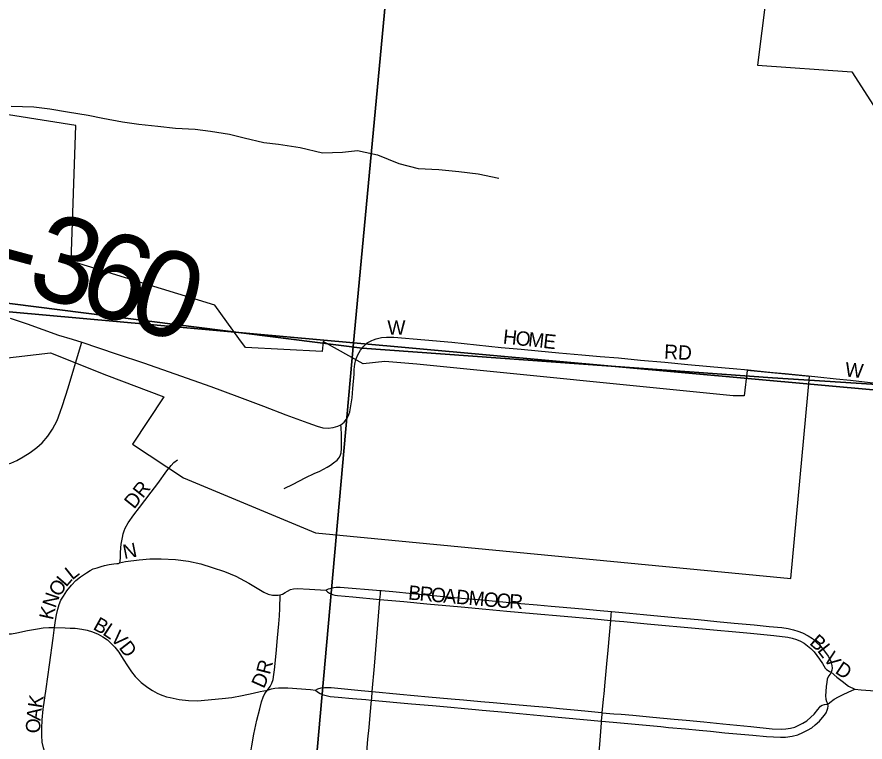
# Model space of a CAD drawing. Extents: x 1410790 to 1770854, y 566777 to 831614.
# Drawn here: x 1598681 to 1601638, y 712950 to 715480 of the extents above; entities that cross this region are included whole.
import ezdxf

# ---------------------------------------------------------------- set-up
doc = ezdxf.new("R2010")
doc.units = 0
for name, color, linetype in [('GM_X_City_Street', 7, 'Continuous'), ('GM_X_City_Street_Text', 7, 'Continuous'), ('GM_X_Corporation', 7, 'Continuous'), ('GM_X_County_Road', 7, 'Continuous'), ('GM_X_County_Road_Text', 7, 'Continuous'), ('GM_X_Minor_River', 7, 'Continuous'), ('GM_X_Section', 7, 'Continuous'), ('GM_X_Township', 7, 'Continuous'), ('GM_X_Township_Subdivision', 7, 'Continuous')]:
    doc.layers.add(name, color=color, linetype=linetype)

msp = doc.modelspace()

# ---------------------------------------------------------------- linework, layer by layer
at = {"layer": 'GM_X_City_Street'}
for points in [[(1598831.1, 714100.5), (1598839.6, 714124.1), (1598858.8, 714185.4), (1598902.2, 714329.5), (1598906.7, 714344.6)], [(1599863.4, 714286.9), (1599868.8, 714301), (1599878.2, 714317.7), (1599883.9, 714324.7), (1599889.6, 714331.7), (1599902.1, 714342.7), (1599917.8, 714351.5), (1599923.9, 714353.8), (1599933.4, 714357.2), (1599951.7, 714361.4), (1599968.8, 714363), (1599994.9, 714363), (1600102.7, 714353.6), (1600197, 714344.7), (1600368.8, 714327), (1600439.2, 714320.8), (1600498, 714314.5), (1600569.9, 714308.3), (1600650.1, 714301.5), (1600713.6, 714295.3), (1600777.7, 714290), (1600854.8, 714282.8), (1600939.2, 714274.9), (1601019.9, 714267.7), (1601150.1, 714255.7), (1601177.9, 714253.1)], [(1601441.1, 714227.7), (1601473.5, 714224.4), (1601536.5, 714217.1), (1601586.5, 714212.4), (1601636, 714207.2), (1601666.2, 714203.6), (1601704.8, 714199.9), (1601789.2, 714190.6), (1601837.1, 714185.3), (1601914.3, 714177.2)], [(1598359.7, 713924.1), (1598490.8, 713914.6), (1598538.5, 713911.1), (1598575, 713910.3), (1598606.2, 713912), (1598631.4, 713916.3), (1598658.7, 713923.5), (1598680, 713932.8), (1598702.6, 713945), (1598726.9, 713959.7), (1598750.1, 713977.6), (1598769, 713993.8), (1598787.7, 714017.3), (1598804.7, 714041.4), (1598820.6, 714071.7), (1598831.1, 714100.5)], [(1599038.1, 713575.7), (1599039.9, 713579.6), (1599040.8, 713583.9), (1599041.6, 713590.8), (1599041.9, 713600.9), (1599041.9, 713610.6), (1599042.8, 713627.9), (1599043.9, 713640), (1599045.9, 713651.9), (1599048, 713663.1), (1599051.4, 713676.3), (1599054.9, 713686.4), (1599058.3, 713695.6), (1599068.1, 713714.4), (1599087.8, 713742.5), (1599107.8, 713768.7), (1599126.4, 713792.6), (1599148.1, 713821.2)], [(1598811, 713349.6), (1598814.8, 713374.2), (1598818.3, 713394.1), (1598822.6, 713413.2), (1598827.8, 713429.7), (1598833.9, 713444.5), (1598842.6, 713459.2), (1598854.7, 713477.4), (1598870.4, 713497.4), (1598886, 713513), (1598901.6, 713526.1), (1598923.3, 713540.8), (1598935.4, 713548.1), (1598946.7, 713553.9), (1598959.8, 713558.2), (1598973.9, 713562.5), (1598985.9, 713565.6), (1599002.2, 713569), (1599018.7, 713571.3), (1599028.5, 713572.3), (1599034.8, 713573.4), (1599036.6, 713574.4), (1599038.1, 713575.7)], [(1599038.1, 713575.7), (1599058.5, 713579.3), (1599106.2, 713586.1), (1599143.3, 713588.7), (1599182.9, 713588.6), (1599233.2, 713586.8), (1599279.2, 713580.8), (1599321.7, 713572.1), (1599361.7, 713559), (1599404.2, 713545.2), (1599443.3, 713528.7), (1599489.3, 713504.4), (1599541.8, 713472.3), (1599556.3, 713466), (1599571.1, 713462.3), (1599582.8, 713462), (1599591.3, 713462.2), (1599598.7, 713463.6)], [(1599598.7, 713463.6), (1599606.5, 713466.4), (1599615.7, 713471.3), (1599623.6, 713476.6), (1599634.5, 713482.1), (1599645, 713484.3), (1599658.1, 713485.1), (1599700.2, 713483.3), (1599757.7, 713479.4)], [(1599757.7, 713479.4), (1599767, 713484.1), (1599776.2, 713487.1), (1599785.4, 713489), (1599793.1, 713490.1), (1599808, 713490), (1599948.7, 713478.8)], [(1599554.5, 713131.3), (1599563.6, 713143.9), (1599569.5, 713155), (1599574.1, 713168.6), (1599576.6, 713185.1), (1599578.1, 713201.4), (1599584.2, 713258.7), (1599589.4, 713313.4), (1599593.7, 713362), (1599596.5, 713390), (1599596.8, 713415.5), (1599598.7, 713463.6)], [(1599757.7, 713479.4), (1599763.6, 713473.7), (1599770.7, 713468.8), (1599780.9, 713464.3), (1599789.2, 713461.9), (1599798, 713460.7), (1599852.2, 713456), (1599946.1, 713447.4)], [(1599946.1, 713447.4), (1599947.6, 713466.1), (1599948.7, 713478.8)], [(1599948.7, 713478.8), (1599951.5, 713478.6), (1599991.2, 713474.7), (1600059.6, 713468.1), (1600180.1, 713456.5), (1600242.9, 713450.8), (1600301, 713445.6), (1600385.9, 713437.9), (1600437.4, 713433.3), (1600493.9, 713428.2), (1600543.3, 713423.7), (1600570.7, 713421.3), (1600652.6, 713414.5), (1600713.6, 713408.8), (1600753.7, 713405.1)], [(1599919.5, 713125.8), (1599926.9, 713214.6), (1599946.1, 713447.4)], [(1599946.1, 713447.4), (1600029.2, 713439.8), (1600109.3, 713432.5), (1600229.9, 713421.5), (1600315.9, 713413.6), (1600388.8, 713407), (1600480.9, 713398.6), (1600588.2, 713388.8), (1600694.3, 713379.2), (1600750.9, 713374)], [(1600750.9, 713374), (1600752.6, 713393.2), (1600753.7, 713405.1)], [(1600753.7, 713405.1), (1600778.7, 713402.8), (1600815.9, 713399.4), (1600865.3, 713394.8), (1600974.6, 713384.5), (1601055.3, 713376.9), (1601120.4, 713370.7), (1601181.1, 713365), (1601250.9, 713358.4), (1601303.7, 713353.4), (1601347.9, 713349.2), (1601369.5, 713345.5), (1601388.1, 713341.4), (1601403.2, 713336.4), (1601419.3, 713330.4), (1601439.9, 713320.8), (1601454.5, 713310.7), (1601466.6, 713299.7), (1601482.2, 713284.6), (1601496.3, 713267), (1601508.9, 713249.9), (1601517.4, 713234.3), (1601520, 713226.7), (1601522.2, 713217), (1601523.1, 713207.3), (1601522.5, 713200.9), (1601519.7, 713193.1)], [(1600721.5, 713052.3), (1600725.9, 713100), (1600727.5, 713118), (1600731.2, 713158.3), (1600737.1, 713222.2), (1600741.5, 713270.8), (1600746.2, 713322.9), (1600750.9, 713374)], [(1600750.9, 713374), (1600796.9, 713370.2), (1600878.5, 713362.5), (1601238.3, 713330.1), (1601319.8, 713321.6), (1601368.3, 713315.7), (1601383.8, 713312.6), (1601398.7, 713307.9), (1601412.8, 713301.7), (1601424.9, 713294.5), (1601436.9, 713285.9), (1601449.1, 713275.9), (1601460.1, 713264.5), (1601470.2, 713252), (1601479.5, 713239), (1601489.3, 713223.7), (1601498.8, 713208.1), (1601503.8, 713203), (1601508.9, 713199.1), (1601513.7, 713195.8), (1601519.7, 713193.1)], [(1598486.9, 713312.1), (1598543.6, 713326.3), (1598562, 713329.4), (1598581.7, 713330.9), (1598606.9, 713330.4), (1598628.8, 713328.4), (1598644.5, 713327.4), (1598661.2, 713327.9), (1598680.4, 713330.9), (1598717.8, 713338.8), (1598752, 713344.6), (1598772.2, 713347.9), (1598791.4, 713349.6), (1598811, 713349.6)], [(1598865.3, 712811.4), (1598854.5, 712818.6), (1598844.1, 712826), (1598832.2, 712836.3), (1598820.1, 712846.7), (1598809.7, 712858.9), (1598800.1, 712871.5), (1598790.9, 712887.2), (1598782.9, 712901.4), (1598776.4, 712917.5), (1598772.8, 712930.1), (1598768.8, 712949.7), (1598767, 712972.3), (1598767, 712997.4), (1598768.8, 713027.8), (1598772.3, 713065.1), (1598781.8, 713135.5), (1598793.9, 713218.8), (1598806.2, 713312.7), (1598811, 713349.6)], [(1598811, 713349.6), (1598848.1, 713348.6), (1598866.5, 713347.6), (1598883.6, 713346.6), (1598907, 713343.8), (1598925.1, 713340.4), (1598944, 713334), (1598963.6, 713325.7), (1598979.9, 713316.6), (1598996.1, 713306.1), (1599009.6, 713293.8), (1599021.8, 713280.4), (1599035.7, 713263), (1599051.2, 713238.5), (1599065.5, 713215.5), (1599080.3, 713194.7), (1599093.1, 713178.9), (1599102.9, 713167.9), (1599113.5, 713157.3), (1599136.5, 713139.6), (1599153.1, 713129.1), (1599169.3, 713120), (1599179.5, 713115.5), (1599188.6, 713112.4), (1599202.5, 713107.9), (1599214.9, 713104.9), (1599246.2, 713098.4), (1599278.3, 713095), (1599310.6, 713094), (1599396.6, 713101.4), (1599429.6, 713105.8), (1599466, 713111.8), (1599504.2, 713120.5), (1599528.5, 713126.6), (1599554.5, 713131.3)], [(1601519.7, 713193.1), (1601515.8, 713187.1), (1601510.4, 713179.2), (1601506.2, 713169.5), (1601504, 713159.2), (1601502.4, 713144.2), (1601500.8, 713126.1), (1601500.2, 713110.5), (1601501.2, 713099.7), (1601503.3, 713091.4), (1601508.3, 713081.9)], [(1601519.7, 713193.1), (1601539.9, 713176.5), (1601557.4, 713161.7), (1601580.4, 713145.2), (1601601.9, 713133.9)], [(1599506.7, 712736.3), (1599502, 712745.5), (1599494.2, 712764.6), (1599487.7, 712793.3), (1599486.3, 712832.4), (1599489.6, 712873), (1599494.7, 712908.9), (1599499.2, 712936.5), (1599506.5, 712977.6), (1599517.3, 713026.1), (1599526.9, 713066), (1599533.4, 713090.3), (1599539.1, 713106), (1599545.4, 713118.8), (1599554.5, 713131.3)], [(1599554.5, 713131.3), (1599568.4, 713135.6), (1599579.6, 713137.9), (1599592.7, 713138.9), (1599624.9, 713138.9), (1599703.9, 713132.6), (1599721.4, 713131.3)], [(1599721.4, 713131.3), (1599729.5, 713135.5), (1599741.5, 713139.2), (1599752.5, 713140.5), (1599761.9, 713140.5), (1599776, 713139.8), (1599799.8, 713137.5), (1599881.2, 713129.5), (1599919.5, 713125.8)], [(1599721.4, 713131.3), (1599728.7, 713124.8), (1599738.1, 713119.6), (1599745, 713116.1), (1599753.5, 713113), (1599772.4, 713109.3), (1599800.7, 713106.7), (1599850.8, 713102.2), (1599897.1, 713098.1), (1599916.9, 713096.3)], [(1601508.3, 713081.9), (1601514.9, 713087.9), (1601530.5, 713099), (1601545.2, 713107.7), (1601560.9, 713115.9), (1601578.7, 713124), (1601601.9, 713133.9)], [(1601601.9, 713133.9), (1601624.1, 713131.7), (1601657.3, 713129.3), (1601705.6, 713125.6), (1601750.9, 713121.1), (1601814.5, 713115.5)], [(1599885.1, 712754), (1599890.8, 712815.1), (1599894.9, 712859.4), (1599900.1, 712914.8), (1599904.3, 712960.1), (1599908.1, 713000.8), (1599912.1, 713043.4), (1599916.9, 713096.3)], [(1599916.9, 713096.3), (1599917.5, 713101.6), (1599919.5, 713125.8)], [(1599916.9, 713096.3), (1600055.8, 713083.7), (1600129.6, 713077), (1600192.9, 713071.2), (1600241.6, 713066.7), (1600279.8, 713063.3), (1600302.5, 713061.2), (1600383.8, 713053.8), (1600530.2, 713040.5), (1600719.2, 713023)], [(1599919.5, 713125.8), (1600015.1, 713117), (1600115.8, 713107.8), (1600194.8, 713100.6), (1600237.1, 713096.7), (1600297.8, 713091.5), (1600341.5, 713087.7), (1600391.6, 713083.3), (1600485.6, 713075.2), (1600528.9, 713071), (1600572.4, 713066.8), (1600623.6, 713061.8), (1600660.2, 713058.3), (1600719.3, 713052.5), (1600721.5, 713052.3)], [(1600719.2, 713023), (1600758.9, 713019.3), (1600925.7, 713003.6), (1600952.4, 713001.1), (1601011.7, 712995.5), (1601059.4, 712991), (1601099.2, 712987.2), (1601148.6, 712982.5), (1601190.4, 712978.6), (1601246.2, 712973.3), (1601294.6, 712968.7), (1601343.5, 712966.3), (1601360.6, 712966.5), (1601383.1, 712970.3), (1601403.1, 712975.5), (1601421.3, 712983.4), (1601437, 712991.2), (1601451.7, 712999.9), (1601463.9, 713009.4), (1601478.6, 713022.4), (1601489.5, 713035), (1601496.7, 713043.7), (1601502.3, 713051.8), (1601506, 713060.8), (1601507.9, 713068.2), (1601508.6, 713074.9), (1601508.3, 713081.9)], [(1600721.5, 713052.3), (1600761.6, 713048.8), (1600787.6, 713046.6), (1600828.5, 713043.1), (1600898, 713037.1), (1600971.6, 713030), (1601014, 713025.9), (1601075.9, 713019.9), (1601141.6, 713013.6), (1601239, 713004.2), (1601313.9, 712996.3), (1601345.8, 712995.3), (1601361.9, 712996.2), (1601377.6, 712998.3), (1601392.6, 713002.2), (1601407.1, 713008.3), (1601421.2, 713015.8), (1601434.7, 713024.2), (1601448.2, 713036.3), (1601460.4, 713047.6), (1601473.4, 713063.4), (1601478.4, 713070.5), (1601483, 713075.5), (1601488.8, 713078.8), (1601495.9, 713081.1), (1601503.4, 713081.8), (1601508.3, 713081.9)], [(1600719.2, 713023), (1600721, 713047.2), (1600721.5, 713052.3)], [(1600689.3, 712690.3), (1600691.6, 712717.1), (1600695.4, 712759.4), (1600700.2, 712812.5), (1600703.9, 712850.6), (1600706.8, 712881.1), (1600712.6, 712941), (1600717.3, 713001.2), (1600718.7, 713016.4), (1600719.2, 713023)]]:
    msp.add_lwpolyline(points, dxfattribs=at)
at = {"layer": 'GM_X_Corporation'}
msp.add_lwpolyline([(1602018.7, 714137.1), (1602306.9, 714117.1), (1602431.6, 715283.3), (1603120.4, 715226.7), (1603168.2, 715777.8), (1603125.6, 715781.5), (1603195.2, 716516.7), (1601889.5, 716618), (1601841.9, 716393.6), (1601557, 716405.2), (1601369.8, 716161), (1601263.3, 715311.8), (1601591.9, 715287.9), (1602035.7, 714597)], close=True, dxfattribs=at)
msp.add_lwpolyline([(1598028.3, 714217.9), (1598797.7, 714307.7), (1598992.9, 714230), (1599192.6, 714154), (1599083.4, 713989.7), (1599260.8, 713871.8), (1599721.8, 713679.8), (1601378.5, 713520.7), (1601443.9, 714225.6), (1601227.1, 714246.8), (1601216.7, 714158), (1601178.2, 714158.2), (1600075.3, 714268.2), (1599962.7, 714277.6), (1599888, 714270.1), (1599748.1, 714347.4), (1599745, 714312.5), (1599477.4, 714326.6), (1599454.6, 714358), (1599370.4, 714473.9), (1598869.4, 714627.3), (1598885.9, 715101.1), (1598151.7, 715217.7)], dxfattribs=at)
at = {"layer": 'GM_X_County_Road'}
for points in [[(1598657.1, 714429.4), (1598716, 714409.1), (1598825.6, 714370), (1598872.8, 714355.8), (1598906.7, 714344.6)], [(1598906.7, 714344.6), (1598965.4, 714325.2), (1599030.4, 714303.3), (1599121.2, 714272.6), (1599230.6, 714234.6), (1599356.1, 714190.3), (1599447.7, 714156.4), (1599540.4, 714121.6), (1599618.6, 714091.9), (1599695.1, 714063.2), (1599727.9, 714051.8), (1599746.7, 714046.6), (1599765.2, 714045.3), (1599783.7, 714047.6), (1599799.3, 714052.3), (1599809.5, 714056.9)], [(1599809.5, 714056.9), (1599822, 714065.6), (1599829.8, 714076), (1599835, 714086.9), (1599841.3, 714102.3), (1599849.6, 714151.1), (1599852.1, 714183.8), (1599855.8, 714233.3), (1599856.3, 714249.4), (1599858.4, 714268.2), (1599862.6, 714284.8), (1599863.4, 714286.9)], [(1601177.9, 714253.1), (1601230.3, 714248.2), (1601293.8, 714241.6), (1601316.9, 714239.6), (1601358.9, 714235.9), (1601441.1, 714227.7)]]:
    msp.add_lwpolyline(points, dxfattribs=at)
at = {"layer": 'GM_X_Minor_River'}
msp.add_lwpolyline([(1598660.9, 715169), (1598738.8, 715166.3), (1598794.7, 715159.9), (1598856.5, 715149.4), (1598928.3, 715136.8), (1598980.2, 715126.4), (1599048, 715113.9), (1599105.8, 715105.4), (1599171.7, 715098.9), (1599233.6, 715092.4), (1599301.5, 715087.9), (1599355.3, 715081.4), (1599421.2, 715070.9), (1599473, 715058.5), (1599540.8, 715041.9), (1599592.7, 715035.5), (1599668.5, 715024.9), (1599746.2, 715006.3), (1599816.2, 715007.8), (1599868.1, 715013.4), (1599937.9, 714998.8), (1600011.6, 714968.2), (1600079.4, 714951.6), (1600151.3, 714947.1), (1600221.1, 714940.5), (1600289, 714932), (1600360.8, 714917.4)], dxfattribs=at)
at = {"layer": 'GM_X_Section'}
for points in [[(1595012.6, 720101.4), (1600348.4, 719616.3), (1599854.3, 714342.5), (1594520.4, 714823.7)], [(1600348.4, 719616.3), (1605628.3, 719130), (1605148.2, 713864), (1599854.3, 714342.5)], [(1599854.3, 714342.5), (1599376.7, 708982.6), (1594039.9, 709527.8), (1594520.4, 714823.7)], [(1599854.3, 714342.5), (1605148.2, 713864), (1604648.8, 708516.3), (1599376.7, 708982.6)]]:
    msp.add_lwpolyline(points, close=True, dxfattribs=at)
at = {"layer": 'GM_X_Township'}
for points in [[(1604201.8, 713960.4), (1603424.4, 714032.7), (1602968.2, 714076), (1602517.3, 714122.9), (1602314.3, 714141.4), (1602286.5, 714143.7), (1602190.7, 714152.5), (1602114.2, 714158.8), (1602082.7, 714161.3), (1601930.8, 714175.5), (1601837.1, 714185.4), (1601789.1, 714190.6), (1601314.8, 714221), (1599883.9, 714324.7), (1598425.6, 714508.9)], [(1598425.6, 714508.9), (1599883.9, 714324.7), (1601314.8, 714221), (1601789.1, 714190.6), (1601837.1, 714185.4), (1601930.8, 714175.5), (1602082.7, 714161.3), (1602114.2, 714158.8), (1602190.7, 714152.5), (1602286.5, 714143.7), (1602314.3, 714141.4), (1602517.3, 714122.9), (1602968.2, 714076), (1603424.4, 714032.7), (1604201.8, 713960.4)]]:
    msp.add_lwpolyline(points, dxfattribs=at)
at = {"layer": 'GM_X_Township_Subdivision'}
for points in [[(1599611.7, 713834.4), (1599643.5, 713850), (1599663.8, 713860.4), (1599687.7, 713872.4), (1599717.4, 713886.5), (1599736.2, 713895.3), (1599762.2, 713909.4), (1599773.7, 713916.2), (1599784.6, 713924), (1599796.6, 713933.3), (1599801.3, 713939.1), (1599804.9, 713944.3), (1599808.6, 713952.1), (1599810.6, 713958.8), (1599811.7, 713974.5), (1599812.2, 713990.1), (1599812.2, 714023.4), (1599810.6, 714046.3), (1599809.5, 714056.9)], [(1599148.1, 713821.2), (1599171.6, 713852.4), (1599203.7, 713895.8), (1599218.4, 713914.9), (1599228, 713925.4), (1599240.1, 713934.9)]]:
    msp.add_lwpolyline(points, dxfattribs=at)

# ---------------------------------------------------------------- texts
at = {"layer": 'GM_X_City_Street_Text'}
for s, rotation, p in [('W', 0, (1599972.1, 714371.3)), ('H', 353.8022, (1600373.6, 714340.5)), ('O', 353.7805, (1600417.3, 714335.7)), ('M', 353.8009, (1600461.1, 714331)), ('E', 353.8147, (1600513.6, 714325.2)), ('RD', 356.989, (1600936.2, 714287.7)), ('W', 353.58, (1601566, 714226.1)), ('DR', 51.3455, (1599089, 713760.3)), ('N', 11.3225, (1599055.1, 713587.9)), ('L', 38.2416, (1598872.9, 713513.3)), ('O', 55.0671, (1598827.4, 713453.4)), ('L', 49.3128, (1598851.8, 713488.4)), ('B', 354.9419, (1600043.4, 713447.3)), ('R', 354.9479, (1600082.8, 713443.8)), ('O', 354.9472, (1600122.3, 713440.3)), ('A', 354.9472, (1600166.1, 713436.4)), ('D', 354.9472, (1600209.9, 713432.6)), ('N', 71.1988, (1598814.9, 713415)), ('M', 354.9468, (1600253.7, 713428.7)), ('O', 354.9472, (1600306.3, 713424)), ('O', 355.4206, (1600350.6, 713420.1)), ('R', 356.9386, (1600395.9, 713416.5)), ('K', 77.3313, (1598805.6, 713373.5)), ('B', 331.0775, (1598942.7, 713344.9)), ('L', 326.5524, (1598976.5, 713326.3)), ('V', 315.0773, (1599003.8, 713308.6)), ('D', 307.4687, (1599033.8, 713278.8)), ('B', 318.8666, (1601441.2, 713292.8)), ('L', 307.6785, (1601469.2, 713268.6)), ('V', 306.2491, (1601490.6, 713241)), ('R', 75.7013, (1599562.3, 713182.9)), ('D', 326.5092, (1601530.2, 713192.5)), ('D', 65.86, (1599541.3, 713134)), ('K', 81.091, (1598767.3, 713066)), ('A', 83.2953, (1598762.3, 713022.8)), ('O', 88.9071, (1598761.5, 712980.1))]:
    msp.add_text(s, height=50, rotation=rotation, dxfattribs=at).set_placement(p)
at = {"layer": 'GM_X_County_Road_Text'}
for s, rotation, p in [('3', 343.423, (1598706.2, 714518.1)), ('6', 341.8574, (1598879.8, 714466.4)), ('-', 344.8786, (1598590.3, 714549.4)), ('0', 340.6797, (1599052.5, 714409.9))]:
    msp.add_text(s, height=300, rotation=rotation, dxfattribs=at).set_placement(p)

doc.saveas('drawing.dxf')
